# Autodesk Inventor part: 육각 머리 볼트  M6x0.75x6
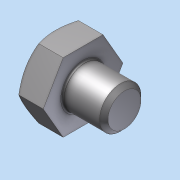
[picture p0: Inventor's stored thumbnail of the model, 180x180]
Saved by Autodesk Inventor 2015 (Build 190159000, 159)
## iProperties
Created: 2024-05
Part Number: 육각 머리 볼트  M6x0.75x6
Material: 일반
Document SubType Name: Modeling
Designer: Administrator
Density: 1 g/cm^3
Appearance: 기본값
Author: Administrator
Author: jhkim
Description: 6각 머리 볼트 및 6각 머리 나사
Creation Date: 2024-05-10
Sending System: Autodesk Inventor 2025
Preprocessor: ST-DEVELOPER v20
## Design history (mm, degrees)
node "육각 머리 볼트  M6x0.75x61"
body "Solid1"
node "기준1"
